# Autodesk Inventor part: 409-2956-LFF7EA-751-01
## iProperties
Created: 2010-06
Part Number: 409-2956-LFF7EA-751-01
Material: Sch40 CS PIPE SEAMLESS
Description: PIPE
Document SubType Name: Modeling
Designer: S. Boerckel
Engineer: Steve Boerckel
Mass: 1123.09 g
Surface Area: 745.373 cm^2
Volume: 143.068 cm^3
Density: 7.85 g/cm^3
Cost Center: 2"
SMR: =<COST CENTER> - <Material>
Length: 8.125 in
Title: 2"
Author: S. Boerckel
Revision Number: B
Subject: DEMIN WATER FORWARDING PUMP SKID-7EA
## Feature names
1. Extrusion1
